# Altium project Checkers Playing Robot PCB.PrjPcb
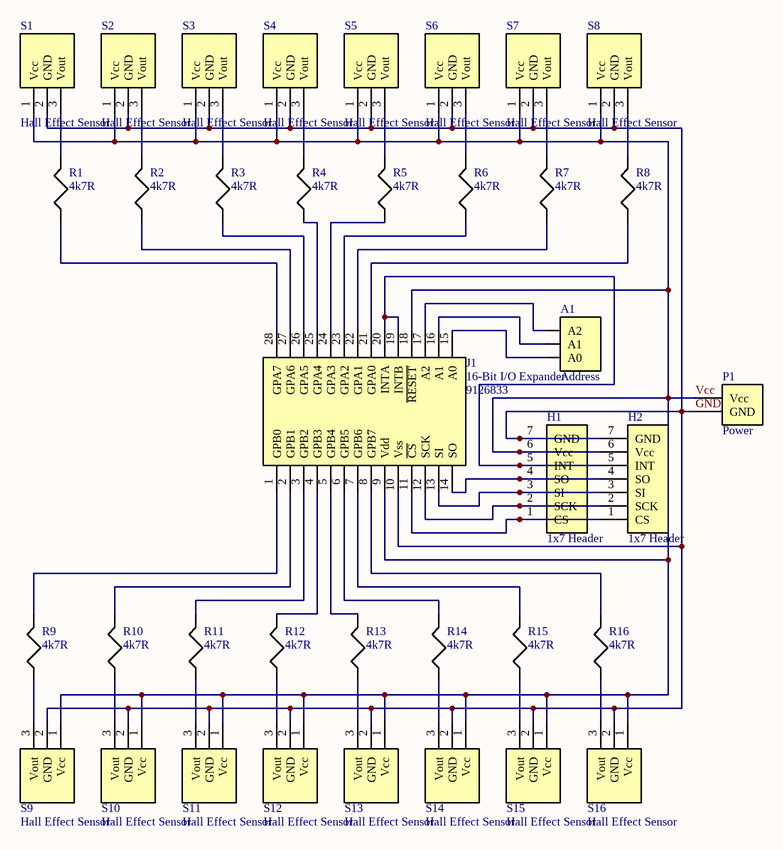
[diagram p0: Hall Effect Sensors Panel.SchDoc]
1 sheet, 37 parts. Net scope: global (net labels, ports and power ports of the same name join across sheets).
Board file: Hall Effect Sensor Panel PCB.PcbDoc

## Sheet Hall Effect Sensors Panel.SchDoc
size A4; SheetNumber: 1; SheetTotal: 1

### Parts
A1  Address  [Address]
H1  1x7 Header  [Molex]
H2  1x7 Header  [Molex]
J1  16-Bit I/O Expander  Supplier Part Number 1: 9126833  [MCP23S17-E/SP]
P1  Power  [Power]
R1  4k7R  [CFR100J4K7]
R2  4k7R  [CFR100J4K7]
R3  4k7R  [CFR100J4K7]
R4  4k7R  [CFR100J4K7]
R5  4k7R  [CFR100J4K7]
R6  4k7R  [CFR100J4K7]
R7  4k7R  [CFR100J4K7]
R8  4k7R  [CFR100J4K7]
R9  4k7R  [CFR100J4K7]
R10  4k7R  [CFR100J4K7]
R11  4k7R  [CFR100J4K7]
R12  4k7R  [CFR100J4K7]
R13  4k7R  [CFR100J4K7]
R14  4k7R  [CFR100J4K7]
R15  4k7R  [CFR100J4K7]
R16  4k7R  [CFR100J4K7]
S1  Hall Effect Sensor  [A1104EUA-T]
S2  Hall Effect Sensor  [A1104EUA-T]
S3  Hall Effect Sensor  [A1104EUA-T]
S4  Hall Effect Sensor  [A1104EUA-T]
S5  Hall Effect Sensor  [A1104EUA-T]
S6  Hall Effect Sensor  [A1104EUA-T]
S7  Hall Effect Sensor  [A1104EUA-T]
S8  Hall Effect Sensor  [A1104EUA-T]
S9  Hall Effect Sensor  [A1104EUA-T]
S10  Hall Effect Sensor  [A1104EUA-T]
S11  Hall Effect Sensor  [A1104EUA-T]
S12  Hall Effect Sensor  [A1104EUA-T]
S13  Hall Effect Sensor  [A1104EUA-T]
S14  Hall Effect Sensor  [A1104EUA-T]
S15  Hall Effect Sensor  [A1104EUA-T]
S16  Hall Effect Sensor  [A1104EUA-T]

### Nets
GND: H1.7(GND) H2.7(GND) J1.10(Vss) P1.2(GND) S1.2(GND) S2.2(GND) S3.2(GND) S4.2(GND) S5.2(GND) S6.2(GND) S7.2(GND) S8.2(GND) S9.2(GND) S10.2(GND) S11.2(GND) S12.2(GND) S13.2(GND) S14.2(GND) S15.2(GND) S16.2(GND)
Vcc: H1.6(Vcc) H2.6(Vcc) J1.9(Vdd) J1.18(~{RESET}) P1.1(Vcc) S1.1(Vcc) S2.1(Vcc) S3.1(Vcc) S4.1(Vcc) S5.1(Vcc) S6.1(Vcc) S7.1(Vcc) S8.1(Vcc) S9.1(Vcc) S10.1(Vcc) S11.1(Vcc) S12.1(Vcc) S13.1(Vcc) S14.1(Vcc) S15.1(Vcc) S16.1(Vcc)
NetA1_1: A1.1(A0) J1.15(A0)
NetA1_2: A1.2(A1) J1.16(A1)
NetA1_3: A1.3(A2) J1.17(A2)
NetH1_1: H1.1(CS) H2.1(CS) J1.11(~{CS})
NetH1_2: H1.2(SCK) H2.2(SCK) J1.12(SCK)
NetH1_3: H1.3(SI) H2.3(SI) J1.13(SI)
NetH1_4: H1.4(SO) H2.4(SO) J1.14(SO)
NetH1_5: H1.5(INT) H2.5(INT) J1.19(INTB) J1.20(INTA)
NetJ1_1: J1.1(GPB0) R9.2
NetJ1_2: J1.2(GPB1) R10.2
NetJ1_3: J1.3(GPB2) R11.2
NetJ1_4: J1.4(GPB3) R12.2
NetJ1_5: J1.5(GPB4) R13.2
NetJ1_6: J1.6(GPB5) R14.2
NetJ1_7: J1.7(GPB6) R15.2
NetJ1_8: J1.8(GPB7) R16.2
NetJ1_21: J1.21(GPA0) R8.1
NetJ1_22: J1.22(GPA1) R7.1
NetJ1_23: J1.23(GPA2) R6.1
NetJ1_24: J1.24(GPA3) R5.1
NetJ1_25: J1.25(GPA4) R4.1
NetJ1_26: J1.26(GPA5) R3.1
NetJ1_27: J1.27(GPA6) R2.1
NetJ1_28: J1.28(GPA7) R1.1
NetR1_2: R1.2 S1.3(Vout)
NetR2_2: R2.2 S2.3(Vout)
NetR3_2: R3.2 S3.3(Vout)
NetR4_2: R4.2 S4.3(Vout)
NetR5_2: R5.2 S5.3(Vout)
NetR6_2: R6.2 S6.3(Vout)
NetR7_2: R7.2 S7.3(Vout)
NetR8_2: R8.2 S8.3(Vout)
NetR9_1: R9.1 S9.3(Vout)
NetR10_1: R10.1 S10.3(Vout)
NetR11_1: R11.1 S11.3(Vout)
NetR12_1: R12.1 S12.3(Vout)
NetR13_1: R13.1 S13.3(Vout)
NetR14_1: R14.1 S14.3(Vout)
NetR15_1: R15.1 S15.3(Vout)
NetR16_1: R16.1 S16.3(Vout)

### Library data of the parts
H1 H2 = 22-23-2071: CONN HEADER VERT 7POS 2.54MM; Number of Contacts: 7; Contact Resistance: 10mR; Gender: Male; Max Voltage Rating (AC): 250V; Current Rating: 4A; Max Current Rating: 10A; Insulation Resistance: 500GR; Approvals: UL,CSA; Glow Wire Compliant: Non-compliant
J1 = MCP23S17-E/SP: TE CONNECTIVITY         CFR100J4K7             Through Hole Resistor, 4.7 kohm, 500 V, Axial Leaded, 1 W,  5%, CFR Series; Manufacturer: Microchip; Interface: SPI,Serial; Nominal Supply Current: 1mA; Number of Channels: 1; Min Supply Voltage: 1.8V; Max Supply Voltage: 5.5V; Number of I/Os: 16; Frequency: 10MHz; Temperature Coefficient: 0ppm/°C; Resistance: 4.7kR; Power Rating: 1W; Voltage Rating: 500V
R1-R16 = CFR100J4K7: TE CONNECTIVITY         CFR100J4K7             Through Hole Resistor, 4.7 kohm, 500 V, Axial Leaded, 1 W,  5%, CFR Series; Temperature Coefficient: 0ppm/°C; Resistance: 4.7kR; Power Rating: 1W; Number of Resistors: 1; Voltage Rating: 500V
S1-S16 = A1104EUA-T: ALLEGRO MICROSYSTEMS - A1104EUA-T - IC, HALL-EFFECT SWITCH SIP-3; Output Current: 25mA; Max Supply Current: 7.5mA; Min Supply Voltage: 3.8V; Max Supply Voltage: 24V; Output Type: Digital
